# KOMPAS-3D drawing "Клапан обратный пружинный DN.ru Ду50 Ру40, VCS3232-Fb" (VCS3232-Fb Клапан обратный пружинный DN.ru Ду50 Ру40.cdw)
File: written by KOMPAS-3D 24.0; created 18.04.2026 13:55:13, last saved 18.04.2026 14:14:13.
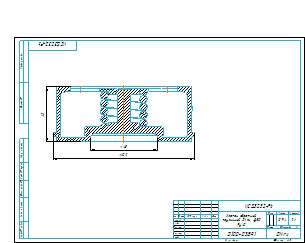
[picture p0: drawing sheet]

Document properties: c3d_UniqueCompID: 071bd168-1a06-425c-849c-e99e84a96128; Наименование: Деталь; Автор: 712; Класс точности: c; Знак неуказанной шероховатости: Шероховатость не задана; Рассекать на разрезах: Да; c3d_UniqueCompID: 071bd168-1a06-425c-849c-e99e84a96128; Наименование: Деталь; Автор: 712; Класс точности: c; Знак неуказанной шероховатости: Шероховатость не задана; Рассекать на разрезах: Да; c3d_UniqueCompID: 071bd168-1a06-425c-849c-e99e84a96128; Наименование: Деталь; Автор: 712; Класс точности: c; Знак неуказанной шероховатости: Шероховатость не задана; Рассекать на разрезах: Да; c3d_UniqueCompID: 071bd168-1a06-425c-849c-e99e84a96128; Наименование: Деталь; Автор: 712; Класс точности: c; Знак неуказанной шероховатости: Шероховатость не задана; Рассекать на разрезах: Да; c3d_UniqueCompID: 071bd168-1a06-425c-849c-e99e84a96128; Наименование: Деталь; Автор: 712; Класс точности: c; Знак неуказанной шероховатости: Шероховатость не задана; Рассекать на разрезах: Да; c3d_UniqueCompID: 071bd168-1a06-425c-849c-e99e84a96128; Наименование: Деталь; Автор: 712; Класс точности: c; Знак неуказанной шероховатости: Шероховатость не задана; Рассекать на разрезах: Да; Автор: 712; Форматы листов документа: A3; Полное имя файла: VCS3232-Fb Клапан обратный пружинный DN.ru Ду50 Ру40.m3d; Масса: 0.94; Наименование: Клапан обратный пружинный DN.ru Ду50 Ру40; Количество листов документа: 1; Примечание: D100-03891

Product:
- Component: Пружина 1086-0966 ГОСТ 18793-80  | qty 1  | additional columns: 3953604318-4147491677-0; Деталь; Пользователь Windows; c; Шероховатость не задана; Да; Сталь 10  ГОСТ 1050-88; source file: Деталь_3.m3d
- Body: Тело 1  | qty 1
    Масса: 0.725562
- Part/product: Клапан обратный пружинный DN.ru Ду50 Ру40  | designation VCS3232-Fb
    Масса: 0.94
    Раздел спецификации: Прочие изделия
    Примечание: D100-03891
    additional columns: 071bd168-1a06-425c-849c-e99e84a96128; Деталь; 712; c; Шероховатость не задана; Да

Views: Вид 1, Местный разрез 1, Спереди
Referenced files in C:\Users\712\Desktop\Новая папка (4)\: VCS3232-Fb Клапан обратный пружинный DN.ru Ду15 Ру40.m3d, VCS3232-Fb Клапан обратный пружинный DN.ru Ду50 Ру40.m3d, VCS3232-Fb Клапан обратный пружинный DN.ru Ду15 Ру40.cdw
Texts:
  VCS3232-Fb
  Клапан обратный
  пружинный DN.ru Ду50
  Ру40
  Клапан обратный пружинный DN.ru Ду50 Ру40
  VCS3232-Fb Клапан обратный пружинный DN.ru Ду50 Ру40
Dimensions and other numbers on the sheet: 0; 3; 2; 4; 102; 48; 40; 2:1; 1; 0,94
